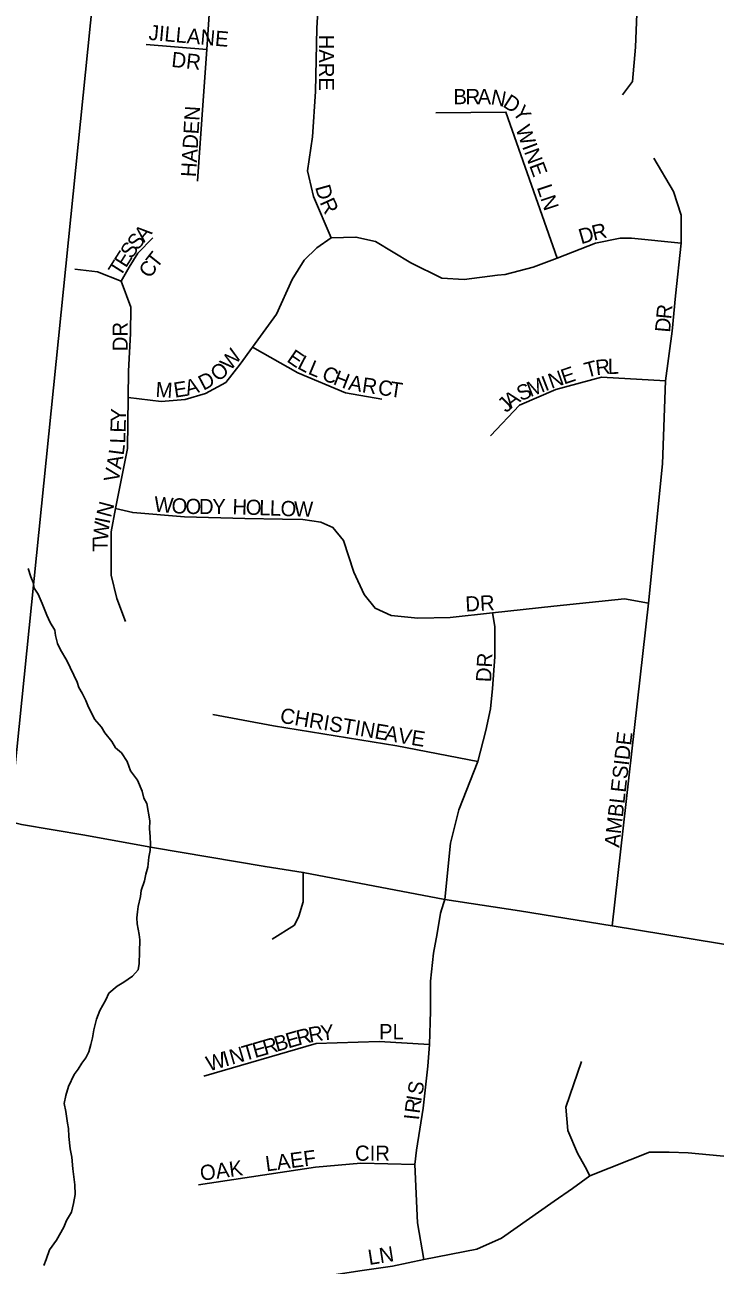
# Model space of a CAD drawing. Extents: x 1310247 to 1552180, y 377264 to 706493.
# Drawn here: x 1439680 to 1441955, y 480751 to 484836 of the extents above; entities that cross this region are included whole.
import ezdxf

# ---------------------------------------------------------------- set-up
doc = ezdxf.new("R2010")
doc.units = 0
for name, color, linetype in [('GM_X_Minor_River', 7, 'Continuous'), ('GM_X_Section', 7, 'Continuous'), ('GM_X_Township_Road', 7, 'Continuous'), ('GM_X_Township_Subdivision', 7, 'Continuous'), ('GM_X_Township_Subdivision_Text', 7, 'Continuous')]:
    doc.layers.add(name, color=color, linetype=linetype)

msp = doc.modelspace()

# ---------------------------------------------------------------- linework, layer by layer
at = {"layer": 'GM_X_Minor_River'}
for points in [[(1440056.5, 481744.3), (1440057.6, 481782.4), (1440058.8, 481822.5), (1440057.3, 481840.6), (1440050.3, 481874.9), (1440048.8, 481895), (1440051.4, 481915), (1440054, 481933), (1440060.9, 481964.9), (1440063.5, 481984.9), (1440074.5, 482016.7), (1440079.1, 482038.7), (1440085.8, 482062.5), (1440088.8, 482094.6), (1440093.4, 482116.5), (1440094, 482136.6), (1440092.8, 482162.7), (1440091.5, 482188.8), (1440092.3, 482214.9), (1440081.9, 482271.4), (1440072.4, 482289.8), (1440067, 482312), (1440052, 482348.6), (1440028.8, 482379.4), (1440017.7, 482409.9), (1439998.5, 482438.6), (1439978.9, 482455.2), (1439967.4, 482475.6), (1439944.2, 482504.5), (1439932.7, 482522.9), (1439909.4, 482549.7), (1439899.9, 482570), (1439890.4, 482588.4), (1439881.1, 482610.8), (1439869.7, 482635.2), (1439858.2, 482653.6), (1439852.7, 482671.8), (1439818.7, 482743.1), (1439797.6, 482777.9), (1439788.2, 482798.3), (1439780.9, 482824.6), (1439779.4, 482842.7), (1439764.1, 482867.3), (1439752.8, 482891.7), (1439737.8, 482930.3), (1439724.7, 482960.8), (1439711.2, 482981.3), (1439707.8, 482999.5), (1439700.3, 483017.8), (1439691, 483046.1)], [(1439742.5, 480750.2), (1439751.1, 480770), (1439762.1, 480801.8), (1439785.1, 480833.2), (1439808.4, 480876.7), (1439817.1, 480898.5), (1439833.9, 480926.1), (1439840.8, 480954), (1439845.7, 480983.9), (1439844.6, 481016.1), (1439838.1, 481068.5), (1439835.2, 481106.7), (1439830, 481135), (1439825.2, 481175.2), (1439823.9, 481201.4), (1439820.4, 481219.5), (1439815.5, 481257.8), (1439810.3, 481284.1), (1439815, 481310), (1439823.9, 481339.9), (1439843.2, 481379.4), (1439855.7, 481397.1), (1439868.3, 481416.8), (1439880.9, 481434.5), (1439891.5, 481454.2), (1439898.2, 481478.1), (1439902.9, 481500.1), (1439907.6, 481526), (1439916.7, 481561.9), (1439927.6, 481589.6), (1439946.7, 481625.2), (1439957.3, 481646.9), (1439984.1, 481670.2), (1440006.6, 481683.6), (1440035.2, 481702.8), (1440053.9, 481724.3), (1440056.5, 481744.3)]]:
    msp.add_lwpolyline(points, dxfattribs=at)
at = {"layer": 'GM_X_Section'}
msp.add_lwpolyline([(1434523.9, 489065.4), (1440171.6, 487550.2), (1439630.2, 482211.5), (1433994.3, 483685)], close=True, dxfattribs=at)
at = {"layer": 'GM_X_Township_Road'}
msp.add_lwpolyline([(1436883.1, 482922.1), (1436972.2, 482898.3), (1437824, 482687.6), (1438030, 482631.8), (1438315.4, 482557.9), (1438429.3, 482527.2), (1438546.8, 482496.4), (1438679, 482467.1), (1438877, 482412.7), (1439076.9, 482358.3), (1439353.4, 482281), (1439669.4, 482202.8), (1439877.8, 482167.5), (1440100.5, 482127.2), (1440471.6, 482063.9), (1440597.5, 482044.6), (1441063.4, 481955.8), (1441309.6, 481918.7), (1441615.2, 481868.3), (1442055, 481796.8)], dxfattribs=at)
at = {"layer": 'GM_X_Township_Subdivision'}
for points in [[(1441871.7, 486530.3), (1441861.3, 486389.2), (1441850.7, 486250.8), (1441837.8, 486034.2), (1441824.3, 485883.9), (1441820.5, 485841.9), (1441816.3, 485795.7), (1441789.9, 485693.9), (1441754.6, 485556.2), (1441737.1, 485360.2), (1441698.6, 484928.1), (1441692.3, 484761.9), (1441682, 484649.3), (1441648.9, 484605.9)], [(1440616, 484336.6), (1440611.6, 484355.1), (1440627.5, 484466.6), (1440638, 484616.9), (1440642.1, 484824.4), (1440660, 485130.2), (1440526.7, 485137.4), (1440583, 485357.7), (1440608.4, 485495)], [(1440249.5, 484320.6), (1440267.9, 484586.9), (1440279.4, 484754.2), (1440307.8, 485166.2), (1440526.7, 485137.4)], [(1440079.8, 484771.6), (1440279.4, 484754.2)], [(1441433.9, 484067.4), (1441265, 484548.5), (1441034.7, 484545.8)], [(1441615.2, 481868.3), (1441734.4, 482931.2), (1441780.7, 483389.7), (1441790.5, 483663.1), (1441812.9, 483827.2), (1441824.2, 483943.6), (1441842.9, 484116.9), (1441842.9, 484209.1), (1441817.4, 484287.4), (1441752.3, 484396.9)], [(1440690, 484134.4), (1440631.7, 484270.3), (1440616, 484336.6)], [(1439998, 483991.4), (1440023.8, 484037.4), (1440053.1, 484083.5), (1440101.6, 484134)], [(1440021.2, 483608.3), (1440130, 483595.4), (1440208, 483602.6), (1440275.2, 483621.4), (1440342.1, 483657.9), (1440390, 483718.3), (1440430.4, 483773.9), (1440509.5, 483883.3), (1440561.2, 483996.9), (1440600.7, 484061), (1440642, 484101.7), (1440690, 484134.4), (1440770.8, 484136.8), (1440835.5, 484122), (1440952, 484052.4), (1441054.4, 484001.2), (1441127.1, 483997.2), (1441237.5, 484011)], [(1441237.5, 484011), (1441262.3, 484014.1), (1441354.8, 484038.1), (1441433.9, 484067.4), (1441560.2, 484117.2), (1441641.1, 484133.3), (1441679, 484133.3), (1441842.9, 484116.9)], [(1439998, 483991.4), (1439919.8, 484022.8), (1439844.6, 484031)], [(1440012.3, 482871.1), (1439983.4, 482946.8), (1439964.8, 483023.3), (1439964.8, 483166.6), (1439979.3, 483243.4), (1440018.5, 483440.8), (1440021.2, 483608.3), (1440022.3, 483695), (1440028.6, 483819.6), (1440029.5, 483906.6), (1439998, 483991.4)], [(1440430.4, 483773.9), (1440579.3, 483689.8), (1440736.3, 483624.1), (1440856.2, 483603.5)], [(1441790.5, 483663.1), (1441580.2, 483675.8), (1441430.1, 483635.1), (1441309.6, 483583.2), (1441214.2, 483482.3)], [(1439979.3, 483243.4), (1440036, 483229.8), (1440206.1, 483215.7), (1440404.6, 483210.5), (1440529.1, 483208), (1440596.6, 483206.7), (1440655.6, 483198.3), (1440695.4, 483181), (1440730, 483138.2), (1440764.1, 483033.9), (1440798.2, 482960.1), (1440834.1, 482914.5), (1440887.4, 482890.8), (1440974.7, 482882.4), (1441082, 482884.3), (1441221.3, 482899.8), (1441422.9, 482921)], [(1441422.9, 482921), (1441655.7, 482945.6), (1441734.4, 482931.2)], [(1441221.3, 482899.8), (1441228.4, 482854.2), (1441228.4, 482754.6), (1441220.7, 482650.6), (1441214.9, 482583.8), (1441199.5, 482511.9), (1441172.5, 482409.8), (1441109.6, 482251.2), (1441082.6, 482140.8), (1441063.4, 481955.8), (1441059.5, 481942.9)], [(1441172.5, 482409.8), (1440906, 482461.2), (1440499.6, 482527.3), (1440299.9, 482564.6)], [(1440495.3, 481825.3), (1440568.2, 481871.3), (1440582.5, 481900.6), (1440596.9, 481947.4), (1440597.5, 482044.6)], [(1441059.5, 481942.9), (1441049.9, 481910.2), (1441038.3, 481844.1), (1441026.1, 481779.3), (1441016.5, 481686.8), (1441016.5, 481587.9), (1441013.1, 481478.4), (1441008.1, 481406.2), (1440992.1, 481268.8), (1440970.9, 481130.1), (1440965.1, 481082.5), (1440973.5, 480890.5), (1440995.3, 480769.8)], [(1441013.1, 481478.4), (1440847.4, 481488.3), (1440640.2, 481480.9), (1440270.1, 481373.5)], [(1441541.1, 481046), (1441525.7, 481074.8), (1441500.7, 481120.4), (1441469.2, 481194.9), (1441462.1, 481271.3), (1441514.1, 481422.2)], [(1439913.2, 480528.1), (1439945.4, 480548.9), (1440011.6, 480586.2), (1440110.5, 480627.3), (1440351.9, 480665.8), (1440591.4, 480703), (1440784.1, 480732.6), (1440891.9, 480748.6), (1440995.3, 480769.8), (1441169.3, 480804.5), (1441250.9, 480839.8), (1441424.2, 480962.5), (1441484, 481003.6), (1441541.1, 481046), (1441738.2, 481123), (1441803.1, 481123.6), (1441866, 481121.1), (1442006.6, 481107.6)], [(1440965.1, 481082.5), (1440787.3, 481087.7), (1440638.3, 481074.2), (1440252.4, 481015.8)]]:
    msp.add_lwpolyline(points, dxfattribs=at)

# ---------------------------------------------------------------- texts
at = {"layer": 'GM_X_Township_Subdivision_Text'}
for s, rotation, p in [('JILLANE', 354.8987, (1440086.7, 484786.7)), ('HARE', 270, (1440649.1, 484803.7)), ('DR', 353.9889, (1440161.6, 484697.7)), ('B', 0, (1441092.4, 484574.6)), ('R', 0, (1441132, 484574.6)), ('A', 0, (1441171.6, 484574.6)), ('N', 349.0735, (1441213.1, 484574.8)), ('D', 327.2205, (1441251.7, 484568.4)), ('Y', 305.3675, (1441285.1, 484548)), ('HADEN', 86.4984, (1440243.9, 484333.5)), ('WINE', 290.4103, (1441295.9, 484494.6)), ('D', 285.6002, (1440636.1, 484301.7)), ('LN', 288.4368, (1441366.4, 484300.7)), ('R', 294.5035, (1440650.8, 484251.5)), ('A', 49.1297, (1440073.3, 484117.5)), ('D', 16.112, (1441513.1, 484113.1)), ('R', 13.3824, (1441554.7, 484125.1)), ('S', 55.3325, (1440031.8, 484062.5)), ('S', 50.4463, (1440051.1, 484090.6)), ('E', 57.5906, (1440013.2, 484033.2)), ('T', 51.3978, (1440114.5, 484030.8)), ('T', 57.5906, (1439994.3, 484003.5)), ('C', 57.7179, (1440094.2, 483998.5)), ('R', 84.3196, (1441809.5, 483865.1)), ('DR', 90, (1440019.3, 483760.9)), ('D', 84.9886, (1441805.7, 483821.4)), ('W', 51.0624, (1440357.8, 483694.1)), ('E', 325.647, (1440540.2, 483729)), ('O', 41.2812, (1440318.3, 483658.4)), ('L', 332.67, (1440575, 483705.7)), ('L', 337.371, (1440610.4, 483687.6)), ('C', 337.5492, (1440655.2, 483669)), ('E', 18.4868, (1441456.3, 483651.2)), ('T', 14.722, (1441530.9, 483673.2)), ('R', 6.9262, (1441563.2, 483681.8)), ('L', 0.4508, (1441601, 483686.4)), ('A', 15.465, (1440215.4, 483614.6)), ('D', 27.7111, (1440268.7, 483630.6)), ('H', 338.9012, (1440693, 483653.4)), ('A', 349.3358, (1440743.6, 483634.8)), ('R', 351.5845, (1440789, 483626.3)), ('C', 351.524, (1440841.2, 483618.6)), ('M', 21.3939, (1441345.8, 483609.5)), ('I', 21.2901, (1441394.9, 483628.7)), ('N', 19.5685, (1441415, 483636.6)), ('M', 356.172, (1440109.8, 483610.8)), ('E', 8.8535, (1440174.5, 483607.8)), ('T', 351.526, (1440880.3, 483612.7)), ('A', 37.2874, (1441281.7, 483570.6)), ('S', 23.4784, (1441313.9, 483595.6)), ('J', 44.2118, (1441267.1, 483556.3)), ('Y', 88.3169, (1440013.1, 483527.5)), ('E', 88.3175, (1440012, 483492.3)), ('L', 87.6996, (1440010.6, 483456.5)), ('L', 82.5137, (1440005.6, 483416.7)), ('A', 79.228, (1439996.9, 483370.4)), ('V', 79.2387, (1439988.7, 483327.1)), ('N', 75.203, (1439963.5, 483211.2)), ('W', 355.1016, (1440104.3, 483233.5)), ('O', 355.8602, (1440162, 483228.6)), ('O', 359.3228, (1440209.2, 483225.3)), ('D', 0.0041, (1440253.9, 483224.7)), ('Y', 0, (1440297.9, 483224.7)), ('H', 357.8902, (1440363.5, 483224.7)), ('O', 357.8793, (1440407.4, 483223.1)), ('L', 357.889, (1440451.4, 483221.5)), ('L', 357.8945, (1440486.6, 483220.2)), ('O', 357.8793, (1440521.8, 483218.9)), ('W', 358.7238, (1440566.5, 483217.2)), ('W', 83.9531, (1439953.4, 483134.7)), ('I', 78.3342, (1439959.2, 483190.3)), ('T', 89.7131, (1439953.3, 483100.9)), ('DR', 3.011, (1441132.6, 482903.5)), ('DR', 86.989, (1441216.1, 482670.2)), ('CHRISTINE', 350.5384, (1440518.6, 482538.2)), ('A', 349.0823, (1440862.2, 482480.9)), ('V', 350.6492, (1440906.9, 482472.3)), ('E', 351.0305, (1440950.7, 482465.1)), ('AMBLESIDE', 83.4188, (1441638.6, 482125.2)), ('Y', 6.0908, (1440657.1, 481490.8)), ('PL', 0, (1440847.1, 481495.5)), ('B', 16.1276, (1440510.1, 481453.9)), ('E', 16.1276, (1440548.2, 481464.9)), ('R', 14.1203, (1440581.5, 481474.5)), ('R', 10.1055, (1440619, 481484)), ('N', 16.1276, (1440362.2, 481411.1)), ('T', 16.1276, (1440404.5, 481423.3)), ('E', 16.1276, (1440438.3, 481433.1)), ('R', 16.1276, (1440472.1, 481442.9)), ('W', 16.1276, (1440286.1, 481389.1)), ('I', 16.1276, (1440341, 481405)), ('S', 80.0324, (1440989.6, 481309.3)), ('R', 82.4246, (1440980.7, 481248.9)), ('I', 80.225, (1440985.9, 481287.7)), ('I', 84.1111, (1440978.5, 481227.4)), ('CIR', 0, (1440767.9, 481095.2)), ('OAK', 7.5939, (1440260.7, 481029.1)), ('LAEF', 7.5938, (1440476.2, 481059.9)), ('LN', 8.9729, (1440814.8, 480751.8))]:
    msp.add_text(s, height=50, rotation=rotation, dxfattribs=at).set_placement(p)

doc.saveas('drawing.dxf')
